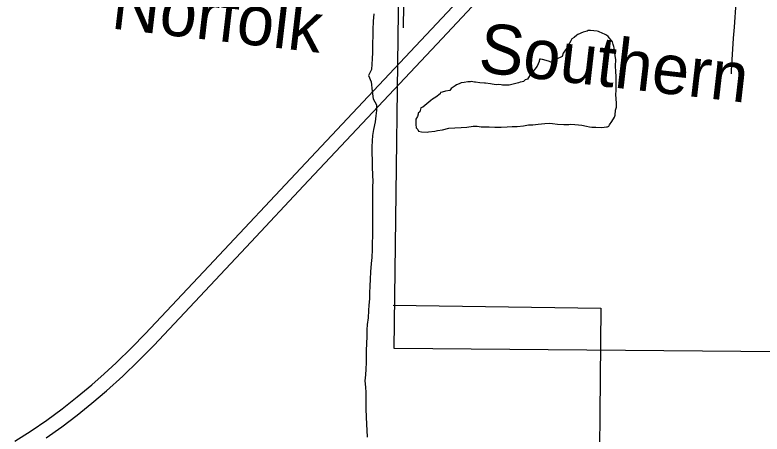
# Model space of a CAD drawing. Extents: x 0 to 34, y 0 to 22.
# Drawn here: x 4.0707 to 4.4958, y 17.8965 to 18.1351 of the extents above; entities that cross this region are included whole.
import ezdxf

# ---------------------------------------------------------------- set-up
doc = ezdxf.new("R2010")
doc.units = 0
for name, color, linetype in [('GM_X_Corporation', 7, 'Continuous'), ('GM_X_Minor_River', 7, 'Continuous'), ('GM_X_Rail_Line_Text', 7, 'Continuous'), ('GM_X_State_Route', 7, 'Continuous'), ('GM_X_Township_Road', 7, 'Continuous')]:
    doc.layers.add(name, color=color, linetype=linetype)

msp = doc.modelspace()

# ---------------------------------------------------------------- linework, layer by layer
at = {"layer": 'GM_X_Corporation'}
msp.add_lwpolyline([(4.78631, 18.43953), (4.79371, 18.43949), (4.7909, 17.94084), (4.28639, 17.94519), (4.29299, 18.44647)], close=True, dxfattribs=at)
at = {"layer": 'GM_X_Minor_River'}
for points in [[(4.27493, 18.13585), (4.27457, 18.13166), (4.27441, 18.12672), (4.27424, 18.1233), (4.27407, 18.11912), (4.2741, 18.1138), (4.27393, 18.11018), (4.27358, 18.1041), (4.27189, 18.10067), (4.27342, 18.09707), (4.27402, 18.09175), (4.27461, 18.08738), (4.27634, 18.08397), (4.27635, 18.08074), (4.27599, 18.0777), (4.27563, 18.07427), (4.2747, 18.0699), (4.27415, 18.06647), (4.27397, 18.06343), (4.2738, 18.06001), (4.27386, 18.0488), (4.27408, 18.04367), (4.27428, 18.04044), (4.27411, 18.03721), (4.2742, 18.0201), (4.27421, 18.01668), (4.27423, 18.01364), (4.27406, 18.00965), (4.27389, 18.00509), (4.27391, 18.00167), (4.27374, 17.99711), (4.27338, 17.99368), (4.27303, 17.98893)], [(4.41073, 18.11978), (4.40828, 18.12283), (4.40734, 18.1236), (4.4062, 18.12418), (4.40526, 18.12457), (4.4028, 18.12572), (4.40204, 18.12592), (4.39824, 18.12633), (4.39691, 18.12634), (4.39634, 18.12596), (4.39406, 18.12541), (4.39101, 18.12391), (4.39044, 18.12354), (4.38891, 18.12222), (4.38757, 18.12147), (4.38699, 18.12034), (4.38449, 18.11599), (4.38257, 18.11334), (4.38199, 18.11145), (4.37894, 18.10995), (4.37818, 18.10977), (4.37646, 18.10845), (4.3757, 18.10827), (4.37494, 18.10865), (4.37305, 18.10924), (4.37096, 18.10982), (4.36982, 18.11002), (4.36925, 18.11002), (4.36905, 18.1087), (4.36789, 18.10605), (4.36655, 18.10435), (4.36559, 18.10322), (4.36502, 18.10265), (4.36445, 18.1019), (4.36233, 18.09849), (4.361, 18.09812), (4.36004, 18.09718), (4.35928, 18.097), (4.35814, 18.09682), (4.35719, 18.09644), (4.35186, 18.09515), (4.34806, 18.09518), (4.3473, 18.09538), (4.34579, 18.09558), (4.34446, 18.0954), (4.34218, 18.0958), (4.34123, 18.09599), (4.33838, 18.09621), (4.33782, 18.09621), (4.33516, 18.09642), (4.33269, 18.09682), (4.33212, 18.09682), (4.33023, 18.09721), (4.32966, 18.09703), (4.32833, 18.09704), (4.32623, 18.09668), (4.32452, 18.0965), (4.32338, 18.09594), (4.32186, 18.09538), (4.32109, 18.09482), (4.31899, 18.09331), (4.31822, 18.09218), (4.31575, 18.09182), (4.31385, 18.09126), (4.3129, 18.09089), (4.3127, 18.09013), (4.31022, 18.08825), (4.30831, 18.08713), (4.30736, 18.08637), (4.30277, 18.08261), (4.30163, 18.08224), (4.30104, 18.07996), (4.30009, 18.07921), (4.30008, 18.07864), (4.29969, 18.07732), (4.29873, 18.0758), (4.29871, 18.07277), (4.29907, 18.07087), (4.30001, 18.06991)], [(4.41068, 18.11982), (4.41073, 18.11978), (4.40828, 18.12283), (4.40734, 18.1236), (4.4062, 18.12418), (4.40526, 18.12457), (4.4028, 18.12572), (4.40204, 18.12592), (4.39824, 18.12633), (4.39691, 18.12634), (4.39634, 18.12596), (4.39406, 18.12541), (4.39101, 18.12391), (4.39044, 18.12354), (4.38891, 18.12222), (4.38757, 18.12147), (4.38699, 18.12034), (4.38449, 18.11599), (4.38257, 18.11334), (4.38199, 18.11145), (4.37894, 18.10995), (4.37818, 18.10977), (4.37646, 18.10845), (4.3757, 18.10827), (4.37494, 18.10865), (4.37305, 18.10924), (4.37096, 18.10982), (4.36982, 18.11002), (4.36925, 18.11002), (4.36905, 18.1087), (4.36789, 18.10605), (4.36655, 18.10435), (4.36559, 18.10322), (4.36502, 18.10265), (4.36445, 18.1019), (4.36233, 18.09849), (4.361, 18.09812), (4.36004, 18.09718), (4.35928, 18.097), (4.35814, 18.09682), (4.35719, 18.09644), (4.35186, 18.09515), (4.34806, 18.09518), (4.3473, 18.09538), (4.34579, 18.09558), (4.34446, 18.0954), (4.34218, 18.0958), (4.34123, 18.09599), (4.33838, 18.09621), (4.33782, 18.09621), (4.33516, 18.09642), (4.33269, 18.09682), (4.33212, 18.09682), (4.33023, 18.09721), (4.32966, 18.09703), (4.32833, 18.09704), (4.32623, 18.09668), (4.32452, 18.0965), (4.32338, 18.09594), (4.32186, 18.09538), (4.32109, 18.09482), (4.31899, 18.09331), (4.31822, 18.09218), (4.31575, 18.09182), (4.31385, 18.09126), (4.3129, 18.09089), (4.3127, 18.09013), (4.31022, 18.08825), (4.30831, 18.08713), (4.30736, 18.08637), (4.30277, 18.08261), (4.30163, 18.08224), (4.30104, 18.07996), (4.30009, 18.07921), (4.30008, 18.07864), (4.29969, 18.07732), (4.29873, 18.0758), (4.29871, 18.07277), (4.29907, 18.07087), (4.30001, 18.06991)], [(4.30001, 18.06991), (4.30039, 18.06896), (4.30209, 18.06857), (4.30532, 18.06835), (4.30608, 18.06854), (4.30969, 18.06889), (4.31121, 18.06926), (4.31407, 18.0698), (4.31749, 18.07073), (4.32091, 18.07089), (4.32452, 18.07106), (4.32775, 18.07122), (4.33136, 18.07176), (4.33364, 18.07175), (4.33592, 18.07135), (4.33801, 18.07134), (4.34048, 18.07151), (4.3437, 18.07129), (4.34731, 18.07127), (4.35073, 18.07143), (4.35358, 18.0716), (4.35643, 18.07158), (4.36004, 18.07193), (4.36289, 18.07248), (4.36536, 18.07265), (4.3684, 18.07301), (4.3722, 18.07336), (4.37486, 18.07353), (4.37657, 18.07332), (4.37942, 18.07292), (4.38302, 18.07271), (4.38587, 18.07269), (4.38701, 18.07287), (4.38929, 18.07285), (4.39138, 18.07264), (4.39328, 18.07244), (4.39593, 18.07185), (4.39764, 18.07146), (4.39897, 18.07126), (4.40124, 18.07124), (4.40466, 18.07103), (4.40732, 18.07139), (4.40789, 18.07138), (4.40865, 18.07176), (4.40904, 18.07251), (4.41038, 18.0744), (4.41192, 18.07686), (4.41231, 18.078), (4.41252, 18.08084), (4.41291, 18.08255), (4.41293, 18.08483), (4.41259, 18.08977), (4.4128, 18.09204), (4.41286, 18.10021), (4.41269, 18.10268), (4.41252, 18.10609), (4.41255, 18.10951), (4.41219, 18.11198), (4.41201, 18.11331), (4.41201, 18.11426), (4.41183, 18.11502), (4.41165, 18.11635), (4.41147, 18.11711), (4.4111, 18.11826), (4.41073, 18.11978)], [(4.27303, 17.98893), (4.27286, 17.98475), (4.27269, 17.98076), (4.27252, 17.97695), (4.27235, 17.97353), (4.27198, 17.96992), (4.27181, 17.96688), (4.27164, 17.9627), (4.27109, 17.95889), (4.27092, 17.95585), (4.27094, 17.95186), (4.27077, 17.94825), (4.2706, 17.94388), (4.27063, 17.93723), (4.27027, 17.93342), (4.2701, 17.93019), (4.26974, 17.92677), (4.27014, 17.92316), (4.27034, 17.92012), (4.27039, 17.91062), (4.2706, 17.90625), (4.27081, 17.90188), (4.27083, 17.89865), (4.27104, 17.89466)], [(4.28584, 17.9698), (4.40412, 17.96826), (4.40137, 17.68812)]]:
    msp.add_lwpolyline(points, dxfattribs=at)
at = {"layer": 'GM_X_State_Route'}
for points in [[(4.07066, 17.89239), (4.0798, 17.8983), (4.08876, 17.90449), (4.09752, 17.91095), (4.10609, 17.91766), (4.11446, 17.92462), (4.12147, 17.93078), (4.1283, 17.93714), (4.1372, 17.94582), (4.1448, 17.95362), (4.18096, 17.9921), (4.23623, 18.051), (4.26281, 18.0793), (4.35863, 18.18138)], [(4.08852, 17.89431), (4.09738, 17.90062), (4.10605, 17.9072), (4.11451, 17.91404), (4.12278, 17.92113), (4.13199, 17.9295), (4.14096, 17.93814), (4.14967, 17.94702), (4.2051, 18.00597), (4.23492, 18.03776), (4.31373, 18.1217), (4.36733, 18.17902)]]:
    msp.add_lwpolyline(points, dxfattribs=at)
at = {"layer": 'GM_X_Township_Road'}
for points in [[(4.29187, 18.12776), (4.29217, 18.15421), (4.29248, 18.17405), (4.29324, 18.18992)], [(4.4785, 18.10169), (4.47849, 18.10325), (4.47873, 18.10949), (4.47958, 18.12196), (4.48017, 18.12818), (4.48102, 18.14221), (4.4823, 18.15843)]]:
    msp.add_lwpolyline(points, dxfattribs=at)

# ---------------------------------------------------------------- texts
at = {"layer": 'GM_X_Rail_Line_Text'}
for s, rotation, p in [('Norfolk', 353.3164, (4.12478, 18.12751)), ('Southern', 353.4072, (4.33374, 18.10279))]:
    msp.add_text(s, height=0.028314, rotation=rotation, dxfattribs=at).set_placement(p)

doc.saveas('drawing.dxf')
